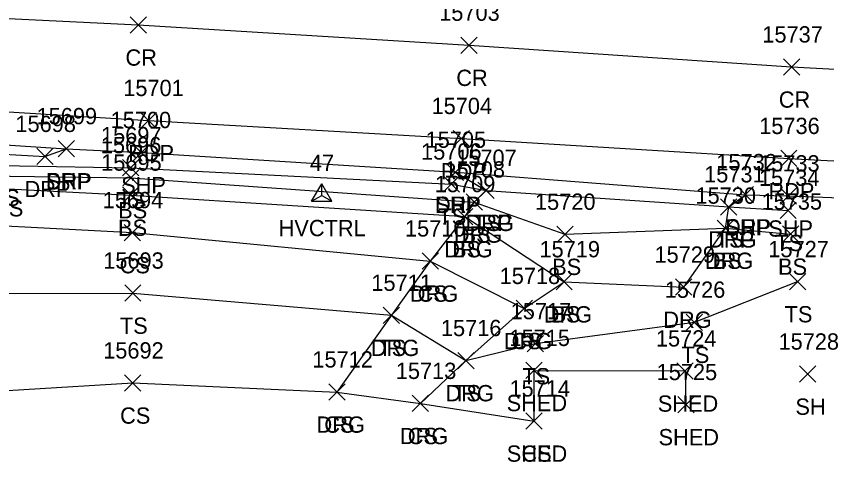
# Model space of a CAD drawing. Extents: x 1606530 to 1613020, y 784959 to 789666.
# Drawn here: x 1609586.7 to 1609686.4, y 788378.1 to 788435.4 of the extents above; entities that cross this region are included whole.
import ezdxf

# ---------------------------------------------------------------- set-up
doc = ezdxf.new("R2010")
doc.units = 0
for name, color, linetype in [('C_A', 7, 'Continuous'), ('C_I', 7, 'Continuous'), ('CPSM', 7, 'Continuous'), ('L_A', 7, 'Continuous'), ('L_I', 7, 'Continuous'), ('L_TIC', 7, 'Continuous'), ('LBC', 7, 'Continuous'), ('LELB', 7, 'Continuous'), ('P_A', 7, 'Continuous'), ('P_I', 7, 'Continuous'), ('P_TIC', 7, 'Continuous'), ('PET', 7, 'Continuous'), ('PRC', 7, 'Continuous'), ('PSP', 7, 'Continuous'), ('R_A', 7, 'Continuous'), ('R_I', 7, 'Continuous'), ('R_TIC', 7, 'Continuous'), ('RDG', 7, 'Continuous'), ('RDP', 7, 'Continuous')]:
    doc.layers.add(name, color=color, linetype=linetype)

msp = doc.modelspace()

# ---------------------------------------------------------------- linework, layer by layer
at = {"layer": 'CPSM'}
for p, q in [((1609623.043, 788412.659), (1609624.293, 788414.824)), ((1609625.543, 788412.659), (1609624.293, 788414.824)), ((1609624.293, 788413.38), (1609624.293, 788414.824)), ((1609623.043, 788412.659), (1609624.293, 788413.38)), ((1609624.293, 788413.38), (1609624.293, 788413.38)), ((1609624.293, 788413.38), (1609625.543, 788412.659)), ((1609623.043, 788412.659), (1609625.543, 788412.659))]:
    msp.add_line(p, q, dxfattribs=at)
at = {"layer": 'L_TIC'}
for points in [[(1609599.795, 788415.784), (1609601.795, 788417.784)], [(1609601.795, 788415.784), (1609599.795, 788417.784)], [(1609599.826, 788414.562), (1609601.826, 788416.562)], [(1609601.826, 788414.562), (1609599.826, 788416.562)], [(1609639.218, 788413.779), (1609641.218, 788415.779)], [(1609641.218, 788413.779), (1609639.218, 788415.779)], [(1609643.481, 788413.008), (1609645.481, 788415.008)], [(1609645.481, 788413.008), (1609643.481, 788415.008)], [(1609599.808, 788412.418), (1609601.808, 788414.418)], [(1609601.808, 788412.418), (1609599.808, 788414.418)], [(1609642.037, 788411.571), (1609644.037, 788413.571)], [(1609644.037, 788411.571), (1609642.037, 788413.571)], [(1609673.304, 788410.98), (1609675.304, 788412.98)], [(1609675.304, 788410.98), (1609673.304, 788412.98)], [(1609680.609, 788410.548), (1609682.609, 788412.548)], [(1609682.609, 788410.548), (1609680.609, 788412.548)], [(1609640.86, 788409.78), (1609642.86, 788411.78)], [(1609642.86, 788409.78), (1609640.86, 788411.78)], [(1609672.894, 788408.365), (1609674.894, 788410.365)], [(1609674.894, 788408.365), (1609672.894, 788410.365)], [(1609600.006, 788407.819), (1609602.006, 788409.819)], [(1609602.006, 788407.819), (1609600.006, 788409.819)], [(1609653.17, 788407.615), (1609655.17, 788409.615)], [(1609655.17, 788407.615), (1609653.17, 788409.615)], [(1609680.926, 788407.637), (1609682.926, 788409.637)], [(1609682.926, 788407.637), (1609680.926, 788409.637)], [(1609636.624, 788404.331), (1609638.624, 788406.331)], [(1609638.624, 788404.331), (1609636.624, 788406.331)], [(1609653.078, 788401.784), (1609655.078, 788403.784)], [(1609655.078, 788401.784), (1609653.078, 788403.784)], [(1609681.766, 788401.8), (1609683.766, 788403.8)], [(1609683.766, 788401.8), (1609681.766, 788403.8)], [(1609600.065, 788400.393), (1609602.065, 788402.393)], [(1609602.065, 788400.393), (1609600.065, 788402.393)], [(1609648.174, 788398.507), (1609650.174, 788400.507)], [(1609650.174, 788398.507), (1609648.174, 788400.507)], [(1609631.84, 788397.668), (1609633.84, 788399.668)], [(1609633.84, 788397.668), (1609631.84, 788399.668)], [(1609669.093, 788396.815), (1609671.093, 788398.815)], [(1609671.093, 788396.815), (1609669.093, 788398.815)], [(1609649.531, 788394.189), (1609651.531, 788396.189)], [(1609651.531, 788394.189), (1609649.531, 788396.189)], [(1609641.012, 788392.109), (1609643.012, 788394.109)], [(1609643.012, 788392.109), (1609641.012, 788394.109)], [(1609649.377, 788390.898), (1609651.377, 788392.898)], [(1609651.377, 788390.898), (1609649.377, 788392.898)], [(1609667.948, 788390.833), (1609669.948, 788392.833)], [(1609669.948, 788390.833), (1609667.948, 788392.833)], [(1609683.015, 788390.451), (1609685.015, 788392.451)], [(1609685.015, 788390.451), (1609683.015, 788392.451)], [(1609600.06, 788389.361), (1609602.06, 788391.361)], [(1609602.06, 788389.361), (1609600.06, 788391.361)], [(1609625.156, 788388.253), (1609627.156, 788390.253)], [(1609627.156, 788388.253), (1609625.156, 788390.253)], [(1609635.409, 788386.851), (1609637.409, 788388.851)], [(1609637.409, 788386.851), (1609635.409, 788388.851)], [(1609668.04, 788386.709), (1609670.04, 788388.709)], [(1609670.04, 788386.709), (1609668.04, 788388.709)], [(1609649.387, 788384.692), (1609651.387, 788386.692)], [(1609651.387, 788384.692), (1609649.387, 788386.692)], [(1609649.387, 788384.692), (1609651.387, 788386.692)], [(1609651.387, 788384.692), (1609649.387, 788386.692)]]:
    msp.add_lwpolyline(points, dxfattribs=at)
at = {"layer": 'LBC'}
msp.add_lwpolyline([(1609650.387, 788385.692), (1609650.377, 788391.898), (1609668.948, 788391.833), (1609669.04, 788387.709)], dxfattribs=at)
at = {"layer": 'LELB'}
for points in [[(1609545.914, 788399.369), (1609528.452, 788409.586), (1609527.019, 788417.085), (1609527.837, 788419.409), (1609531.709, 788420.698), (1609565.718, 788419.168), (1609572.374, 788418.251), (1609577.09, 788417.591), (1609582.555, 788417.105), (1609600.795, 788416.784), (1609640.218, 788414.779), (1609644.481, 788414.008)], [(1609529.36, 788418.477), (1609568.077, 788416.812), (1609576.755, 788416.31), (1609582.999, 788415.805), (1609600.826, 788415.562), (1609643.037, 788412.571), (1609654.17, 788408.615), (1609673.894, 788409.365), (1609681.926, 788408.637)], [(1609580.996, 788414.456), (1609600.808, 788413.418), (1609641.86, 788410.78), (1609654.078, 788402.784)], [(1609674.304, 788411.98), (1609681.609, 788411.548)], [(1609528.452, 788409.586), (1609530.756, 788411.756), (1609572.941, 788410.301), (1609601.006, 788408.819), (1609637.624, 788405.331), (1609649.174, 788399.507)], [(1609531.308, 788396.197), (1609545.914, 788399.369), (1609572.625, 788401.338), (1609601.065, 788401.393), (1609632.84, 788398.668), (1609642.012, 788393.109), (1609650.531, 788395.189), (1609670.093, 788397.815), (1609682.766, 788402.8)], [(1609539.845, 788380.855), (1609574.247, 788388.73), (1609601.06, 788390.361), (1609626.156, 788389.253), (1609636.409, 788387.851), (1609650.387, 788385.692)]]:
    msp.add_lwpolyline(points, dxfattribs=at)
at = {"layer": 'P_TIC'}
for points in [[(1609600.73, 788433.311), (1609602.73, 788435.311)], [(1609602.73, 788433.311), (1609600.73, 788435.311)], [(1609641.39, 788430.817), (1609643.39, 788432.817)], [(1609643.39, 788430.817), (1609641.39, 788432.817)], [(1609681.025, 788428.153), (1609683.025, 788430.153)], [(1609683.025, 788428.153), (1609681.025, 788430.153)], [(1609601.993, 788421.58), (1609603.993, 788423.58)], [(1609603.993, 788421.58), (1609601.993, 788423.58)], [(1609640.45, 788419.372), (1609642.45, 788421.372)], [(1609642.45, 788419.372), (1609640.45, 788421.372)], [(1609591.879, 788418.118), (1609593.879, 788420.118)], [(1609593.879, 788418.118), (1609591.879, 788420.118)], [(1609601.095, 788417.646), (1609603.095, 788419.646)], [(1609603.095, 788417.646), (1609601.095, 788419.646)], [(1609680.697, 788416.919), (1609682.697, 788418.919)], [(1609682.697, 788416.919), (1609680.697, 788418.919)], [(1609639.716, 788415.227), (1609641.716, 788417.227)], [(1609641.716, 788415.227), (1609639.716, 788417.227)], [(1609675.371, 788412.467), (1609677.371, 788414.467)], [(1609677.371, 788412.467), (1609675.371, 788414.467)], [(1609680.631, 788412.321), (1609682.631, 788414.321)], [(1609682.631, 788412.321), (1609680.631, 788414.321)]]:
    msp.add_lwpolyline(points, dxfattribs=at)
at = {"layer": 'PET'}
msp.add_lwpolyline([(1608827.199, 788266.245), (1608867.859, 788290.541), (1608906.681, 788312.856), (1608942.677, 788332.755), (1608980.541, 788352.164), (1609023.571, 788373.225), (1609061.437, 788389.904), (1609090.798, 788401.175), (1609121.915, 788410.089), (1609165.169, 788419.998), (1609195.853, 788425.54), (1609240.139, 788431.13), (1609287.877, 788434.372), (1609331.481, 788435.115), (1609378.889, 788434.051), (1609425.427, 788432.251), (1609443.83, 788431.331), (1609477.321, 788429.782), (1609518.441, 788427.602), (1609569.185, 788424.684), (1609602.993, 788422.58), (1609641.45, 788420.372), (1609681.697, 788417.919), (1609727.381, 788415.531)], dxfattribs=at)
at = {"layer": 'PRC'}
msp.add_lwpolyline([(1608863.252, 788300.903), (1608901.811, 788322.596), (1608937.609, 788342.722), (1608976.118, 788362.757), (1609017.577, 788382.951), (1609062.579, 788402.235), (1609089.789, 788412.891), (1609118.805, 788421.444), (1609162.845, 788431.752), (1609194.146, 788437.356), (1609237.64, 788442.85), (1609286.897, 788446.16), (1609332.711, 788446.436), (1609379.393, 788445.342), (1609425.621, 788443.432), (1609445.831, 788442.47), (1609477.779, 788440.947), (1609519.757, 788438.847), (1609569.723, 788435.898), (1609601.73, 788434.311), (1609642.39, 788431.817), (1609682.025, 788429.153), (1609726.546, 788426.785)], dxfattribs=at)
at = {"layer": 'PSP'}
msp.add_lwpolyline([(1609378.916, 788430.276), (1609425.006, 788428.307), (1609442.997, 788427.344), (1609476.794, 788425.47), (1609487.206, 788424.704), (1609502.755, 788423.67), (1609527.752, 788422.974), (1609569.132, 788420.677), (1609592.879, 788419.118), (1609602.095, 788418.646), (1609640.716, 788416.227), (1609676.371, 788413.467), (1609681.631, 788413.321), (1609727.396, 788411.579)], dxfattribs=at)
at = {"layer": 'R_TIC'}
for points in [[(1609591.879, 788418.118), (1609593.879, 788420.118)], [(1609593.879, 788418.118), (1609591.879, 788420.118)], [(1609589.271, 788417.17), (1609591.271, 788419.17)], [(1609591.271, 788417.17), (1609589.271, 788419.17)], [(1609639.716, 788415.227), (1609641.716, 788417.227)], [(1609641.716, 788415.227), (1609639.716, 788417.227)], [(1609643.481, 788413.008), (1609645.481, 788415.008)], [(1609645.481, 788413.008), (1609643.481, 788415.008)], [(1609643.481, 788413.008), (1609645.481, 788415.008)], [(1609645.481, 788413.008), (1609643.481, 788415.008)], [(1609675.371, 788412.467), (1609677.371, 788414.467)], [(1609677.371, 788412.467), (1609675.371, 788414.467)], [(1609642.037, 788411.571), (1609644.037, 788413.571)], [(1609644.037, 788411.571), (1609642.037, 788413.571)], [(1609673.304, 788410.98), (1609675.304, 788412.98)], [(1609675.304, 788410.98), (1609673.304, 788412.98)], [(1609673.304, 788410.98), (1609675.304, 788412.98)], [(1609675.304, 788410.98), (1609673.304, 788412.98)], [(1609640.86, 788409.78), (1609642.86, 788411.78)], [(1609642.86, 788409.78), (1609640.86, 788411.78)], [(1609672.894, 788408.365), (1609674.894, 788410.365)], [(1609674.894, 788408.365), (1609672.894, 788410.365)], [(1609636.624, 788404.331), (1609638.624, 788406.331)], [(1609638.624, 788404.331), (1609636.624, 788406.331)], [(1609653.078, 788401.784), (1609655.078, 788403.784)], [(1609655.078, 788401.784), (1609653.078, 788403.784)], [(1609667.78, 788401.127), (1609669.78, 788403.127)], [(1609669.78, 788401.127), (1609667.78, 788403.127)], [(1609648.174, 788398.507), (1609650.174, 788400.507)], [(1609650.174, 788398.507), (1609648.174, 788400.507)], [(1609631.84, 788397.668), (1609633.84, 788399.668)], [(1609633.84, 788397.668), (1609631.84, 788399.668)], [(1609641.012, 788392.109), (1609643.012, 788394.109)], [(1609643.012, 788392.109), (1609641.012, 788394.109)], [(1609625.156, 788388.253), (1609627.156, 788390.253)], [(1609627.156, 788388.253), (1609625.156, 788390.253)], [(1609635.409, 788386.851), (1609637.409, 788388.851)], [(1609637.409, 788386.851), (1609635.409, 788388.851)]]:
    msp.add_lwpolyline(points, dxfattribs=at)
at = {"layer": 'RDG'}
for points in [[(1609644.481, 788414.008), (1609643.037, 788412.571), (1609641.86, 788410.78), (1609637.624, 788405.331), (1609632.84, 788398.668), (1609626.156, 788389.253)], [(1609636.409, 788387.851), (1609642.012, 788393.109), (1609649.174, 788399.507), (1609654.078, 788402.784), (1609668.78, 788402.127), (1609673.894, 788409.365), (1609674.304, 788411.98)]]:
    msp.add_lwpolyline(points, dxfattribs=at)
at = {"layer": 'RDP'}
for points in [[(1609569.132, 788420.677), (1609572.347, 788419.164), (1609590.271, 788418.17), (1609592.879, 788419.118)], [(1609640.716, 788416.227), (1609644.481, 788414.008), (1609674.304, 788411.98), (1609676.371, 788413.467)]]:
    msp.add_lwpolyline(points, dxfattribs=at)

# ---------------------------------------------------------------- texts
at = {"layer": 'C_A'}
msp.add_text('HVCTRL', height=2, dxfattribs=at).set_placement((1609618.986, 788408.38))
at = {"layer": 'C_I'}
msp.add_text('47', height=2, dxfattribs=at).set_placement((1609622.829, 788416.38))
at = {"layer": 'L_A'}
for s, p in [('WALLS', (1609578.098, 788412.105)), ('TS', (1609599.205, 788411.784)), ('WALLS', (1609578.542, 788410.805)), ('BS', (1609599.267, 788410.562)), ('TS', (1609638.627, 788409.779)), ('TS', (1609642.89, 788409.008)), ('BS', (1609599.249, 788408.418)), ('BS', (1609641.478, 788407.571)), ('TS', (1609672.714, 788406.98)), ('TS', (1609680.019, 788406.548)), ('BS', (1609640.301, 788405.78)), ('BS', (1609672.335, 788404.365)), ('CS', (1609599.447, 788403.819)), ('BS', (1609652.611, 788403.615)), ('BS', (1609680.367, 788403.637)), ('CS', (1609636.065, 788400.331)), ('BS', (1609652.519, 788397.784)), ('TS', (1609681.176, 788397.8)), ('TS', (1609599.474, 788396.393)), ('CS', (1609647.615, 788394.507)), ('TS', (1609631.25, 788393.668)), ('TS', (1609668.502, 788392.815)), ('TS', (1609648.941, 788390.189)), ('TS', (1609640.422, 788388.109)), ('SHED', (1609647.014, 788386.898)), ('SHED', (1609665.586, 788386.833)), ('SH', (1609682.503, 788386.451)), ('CS', (1609599.501, 788385.361)), ('CS', (1609624.597, 788384.253)), ('CS', (1609634.85, 788382.851)), ('SHED', (1609665.678, 788382.709)), ('SHED', (1609647.025, 788380.692)), ('CS', (1609648.828, 788380.692))]:
    msp.add_text(s, height=2, dxfattribs=at).set_placement(p)
at = {"layer": 'L_I'}
for s, p in [('15697', (1609597.158, 788419.784)), ('15696', (1609597.133, 788418.562)), ('15706', (1609636.493, 788417.779)), ('15707', (1609640.812, 788417.008)), ('15695', (1609597.171, 788416.418)), ('15708', (1609639.368, 788415.571)), ('15731', (1609671.281, 788414.98)), ('15734', (1609678.019, 788414.548)), ('15709', (1609638.183, 788413.78)), ('15730', (1609670.217, 788412.365)), ('15694', (1609597.368, 788411.819)), ('15720', (1609650.493, 788411.615)), ('15735', (1609678.336, 788411.637)), ('15710', (1609634.514, 788408.331)), ('15719', (1609651.047, 788405.784)), ('15727', (1609679.176, 788405.8)), ('15693', (1609597.427, 788404.393)), ('15718', (1609646.151, 788402.507)), ('15711', (1609630.384, 788401.668)), ('15726', (1609666.447, 788400.815)), ('15717', (1609647.508, 788398.189)), ('15716', (1609638.934, 788396.109)), ('15715', (1609647.353, 788394.898)), ('15724', (1609665.358, 788394.833)), ('15728', (1609680.425, 788394.451)), ('15692', (1609597.423, 788393.361)), ('15712', (1609623.133, 788392.253)), ('15713', (1609633.385, 788390.851)), ('15725', (1609665.45, 788390.709)), ('15714', (1609647.364, 788388.692)), ('15714', (1609647.364, 788388.692))]:
    msp.add_text(s, height=2, dxfattribs=at).set_placement(p)
at = {"layer": 'P_A'}
for s, p in [('CR', (1609600.163, 788429.311)), ('CR', (1609640.823, 788426.817)), ('CR', (1609680.458, 788424.153)), ('RDP', (1609600.481, 788417.58)), ('RDP', (1609638.938, 788415.372)), ('SHP', (1609590.414, 788414.118)), ('SHP', (1609599.631, 788413.646)), ('RDP', (1609679.185, 788412.919)), ('SHP', (1609638.252, 788411.227)), ('SHP', (1609673.906, 788408.467)), ('SHP', (1609679.166, 788408.321))]:
    msp.add_text(s, height=2, dxfattribs=at).set_placement(p)
at = {"layer": 'P_I'}
for s, p in [('15703', (1609638.721, 788434.817)), ('15737', (1609678.435, 788432.153)), ('15701', (1609599.891, 788425.58)), ('15704', (1609637.781, 788423.372)), ('15699', (1609589.234, 788422.118)), ('15700', (1609598.34, 788421.646)), ('15736', (1609678.051, 788420.919)), ('15705', (1609637.047, 788419.227)), ('15732', (1609672.78, 788416.467)), ('15733', (1609678.04, 788416.321))]:
    msp.add_text(s, height=2, dxfattribs=at).set_placement(p)
at = {"layer": 'R_A'}
for s, p in [('DRP', (1609590.367, 788414.118)), ('DRP', (1609587.759, 788413.17)), ('DRP', (1609638.204, 788411.227)), ('DRG', (1609641.969, 788409.008)), ('DRP', (1609641.969, 788409.008)), ('DRP', (1609673.859, 788408.467)), ('DRG', (1609640.525, 788407.571)), ('DRG', (1609671.792, 788406.98)), ('DRP', (1609671.792, 788406.98)), ('DRG', (1609639.348, 788405.78)), ('DRG', (1609671.382, 788404.365)), ('DRG', (1609635.112, 788400.331)), ('DRG', (1609651.567, 788397.784)), ('DRG', (1609666.268, 788397.127)), ('DRG', (1609646.662, 788394.507)), ('DRG', (1609630.329, 788393.668)), ('DRG', (1609639.5, 788388.109)), ('DRG', (1609623.644, 788384.253)), ('DRG', (1609633.897, 788382.851))]:
    msp.add_text(s, height=2, dxfattribs=at).set_placement(p)
at = {"layer": 'R_I'}
for s, p in [('15699', (1609589.234, 788422.118)), ('15698', (1609586.633, 788421.17)), ('15705', (1609637.047, 788419.227)), ('15707', (1609640.812, 788417.008)), ('15707', (1609640.812, 788417.008)), ('15732', (1609672.78, 788416.467)), ('15708', (1609639.368, 788415.571)), ('15731', (1609671.281, 788414.98)), ('15731', (1609671.281, 788414.98)), ('15709', (1609638.183, 788413.78)), ('15730', (1609670.217, 788412.365)), ('15710', (1609634.514, 788408.331)), ('15719', (1609651.047, 788405.784)), ('15729', (1609665.182, 788405.127)), ('15718', (1609646.151, 788402.507)), ('15711', (1609630.384, 788401.668)), ('15716', (1609638.934, 788396.109)), ('15712', (1609623.133, 788392.253)), ('15713', (1609633.385, 788390.851))]:
    msp.add_text(s, height=2, dxfattribs=at).set_placement(p)

doc.saveas('drawing.dxf')
